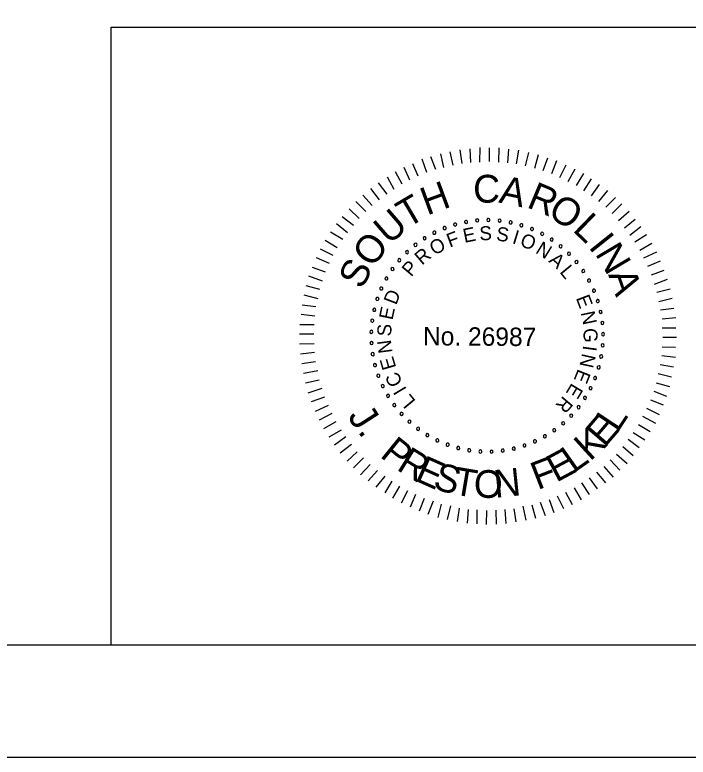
# Model space of a CAD drawing. Extents: x -305 to -161, y -187 to -99.
# Drawn here: x -216.35 to -204.37, y -187.49 to -174.27 of the extents above; entities that cross this region are included whole.
import ezdxf

# ---------------------------------------------------------------- set-up
doc = ezdxf.new("R2010")
doc.units = 0
for name, color, linetype in [('BR_BORDER LINES', 7, 'Continuous'), ('BR_TEXT', 7, 'Continuous'), ('Level 31', 7, 'Continuous')]:
    doc.layers.add(name, color=color, linetype=linetype)

msp = doc.modelspace()

# ---------------------------------------------------------------- linework, layer by layer
at = {"layer": 'BR_BORDER LINES'}
for p, q in [((-214.64, -174.489), (-193.18, -174.489)), ((-214.64, -185.489), (-214.64, -174.489)), ((-297.843, -185.489), (-163.178, -185.489))]:
    msp.add_line(p, q, dxfattribs=at)
at = {"layer": 'BR_TEXT'}
for p, q in [((-208.717, -176.986), (-208.77, -176.742)), ((-208.552, -176.946), (-208.608, -176.709)), ((-208.394, -176.917), (-208.429, -176.673)), ((-208.236, -176.901), (-208.251, -176.657)), ((-208.077, -176.892), (-208.075, -176.634)), ((-207.909, -176.883), (-207.907, -176.636)), ((-207.741, -176.895), (-207.732, -176.637)), ((-207.58, -176.906), (-207.561, -176.663)), ((-207.426, -176.925), (-207.382, -176.681)), ((-207.265, -176.957), (-207.208, -176.721)), ((-209.02, -177.076), (-209.103, -176.842)), ((-208.861, -177.026), (-208.949, -176.795)), ((-207.1, -176.999), (-207.036, -176.756)), ((-206.953, -177.042), (-206.865, -176.813)), ((-206.795, -177.095), (-206.708, -176.862)), ((-209.323, -177.211), (-209.427, -176.987)), ((-209.175, -177.144), (-209.269, -176.92)), ((-206.652, -177.165), (-206.54, -176.942)), ((-206.508, -177.234), (-206.383, -177.012)), ((-209.461, -177.282), (-209.582, -177.065)), ((-206.358, -177.308), (-206.229, -177.093)), ((-209.726, -177.462), (-209.883, -177.258)), ((-209.602, -177.377), (-209.724, -177.16)), ((-206.225, -177.405), (-206.089, -177.19)), ((-209.861, -177.564), (-210.021, -177.363)), ((-206.091, -177.492), (-205.946, -177.291)), ((-205.962, -177.596), (-205.799, -177.398)), ((-209.993, -177.662), (-210.159, -177.482)), ((-205.836, -177.696), (-205.663, -177.519)), ((-210.11, -177.771), (-210.287, -177.594)), ((-205.723, -177.807), (-205.55, -177.634)), ((-210.228, -177.894), (-210.402, -177.724)), ((-205.611, -177.932), (-205.421, -177.765)), ((-210.328, -178.02), (-210.526, -177.864)), ((-205.502, -178.06), (-205.316, -177.907)), ((-210.432, -178.153), (-210.63, -177.993)), ((-205.407, -178.194), (-205.21, -178.038)), ((-210.519, -178.269), (-210.735, -178.137)), ((-205.319, -178.312), (-205.109, -178.183)), ((-210.617, -178.416), (-210.832, -178.287)), ((-205.231, -178.46), (-205.017, -178.335)), ((-210.686, -178.552), (-210.912, -178.441)), ((-210.756, -178.699), (-210.985, -178.598)), ((-205.16, -178.598), (-204.929, -178.49)), ((-205.089, -178.746), (-204.862, -178.648)), ((-210.826, -178.853), (-211.059, -178.766)), ((-205.022, -178.901), (-204.795, -178.817)), ((-210.876, -179.014), (-211.122, -178.923)), ((-204.968, -179.063), (-204.738, -178.976)), ((-210.925, -179.158), (-211.168, -179.098)), ((-210.954, -179.326), (-211.204, -179.262)), ((-204.928, -179.207), (-204.688, -179.151)), ((-204.895, -179.376), (-204.654, -179.316)), ((-210.996, -179.47), (-211.24, -179.437)), ((-204.862, -179.52), (-204.625, -179.491)), ((-211.015, -179.634), (-211.261, -179.605)), ((-204.836, -179.685), (-204.592, -179.66)), ((-211.026, -179.792), (-211.284, -179.79)), ((-204.831, -179.843), (-204.59, -179.845)), ((-211.034, -179.957), (-211.285, -179.955)), ((-204.822, -180.008), (-204.578, -180.01)), ((-211.029, -180.129), (-211.286, -180.133)), ((-204.833, -180.18), (-204.593, -180.189)), ((-211.02, -180.283), (-211.267, -180.312)), ((-211.004, -180.448), (-211.248, -180.484)), ((-204.841, -180.334), (-204.598, -180.367)), ((-204.87, -180.499), (-204.634, -180.538)), ((-210.964, -180.606), (-211.215, -180.659)), ((-204.906, -180.656), (-204.666, -180.713)), ((-210.938, -180.775), (-211.182, -180.831)), ((-204.942, -180.824), (-204.702, -180.885)), ((-210.891, -180.923), (-211.139, -181.006)), ((-204.984, -180.971), (-204.755, -181.059)), ((-210.845, -181.077), (-211.079, -181.161)), ((-210.777, -181.226), (-211.008, -181.334)), ((-205.04, -181.125), (-204.814, -181.213)), ((-210.71, -181.37), (-210.937, -181.489)), ((-205.11, -181.272), (-204.884, -181.384)), ((-205.183, -181.416), (-204.954, -181.538)), ((-210.642, -181.519), (-210.859, -181.644)), ((-205.257, -181.563), (-205.045, -181.692)), ((-210.547, -181.667), (-210.765, -181.792)), ((-205.347, -181.71), (-205.139, -181.839)), ((-210.462, -181.784), (-210.663, -181.93)), ((-205.437, -181.826), (-205.243, -181.975)), ((-210.361, -181.919), (-210.561, -182.075)), ((-205.535, -181.959), (-205.351, -182.118)), ((-210.262, -182.054), (-210.439, -182.217)), ((-210.146, -182.158), (-210.326, -182.338)), ((-205.645, -182.092), (-205.458, -182.258)), ((-210.031, -182.279), (-210.2, -182.463)), ((-205.76, -182.194), (-205.589, -182.377)), ((-209.901, -182.383), (-210.064, -182.57)), ((-206.002, -182.415), (-205.842, -182.605)), ((-205.874, -182.313), (-205.704, -182.5)), ((-209.768, -182.487), (-209.928, -182.678)), ((-206.133, -182.517), (-205.99, -182.71)), ((-209.645, -182.574), (-209.77, -182.782)), ((-209.505, -182.664), (-209.63, -182.879)), ((-206.402, -182.69), (-206.277, -182.907)), ((-206.268, -182.602), (-206.135, -182.812)), ((-209.368, -182.744), (-209.477, -182.967)), ((-209.221, -182.814), (-209.319, -183.037)), ((-206.554, -182.768), (-206.432, -182.992)), ((-209.068, -182.884), (-209.155, -183.11)), ((-208.91, -182.933), (-209.001, -183.166)), ((-207.002, -182.949), (-206.918, -183.183)), ((-206.843, -182.902), (-206.759, -183.13)), ((-206.699, -182.835), (-206.591, -183.059)), ((-208.766, -182.983), (-208.823, -183.219)), ((-208.602, -183.011), (-208.662, -183.258)), ((-208.444, -183.057), (-208.484, -183.29)), ((-208.287, -183.076), (-208.306, -183.323)), ((-208.129, -183.087), (-208.131, -183.335)), ((-207.961, -183.099), (-207.963, -183.343)), ((-207.792, -183.09), (-207.787, -183.338)), ((-207.631, -183.081), (-207.616, -183.329)), ((-207.476, -183.065), (-207.437, -183.299)), ((-207.315, -183.022), (-207.262, -183.27)), ((-207.15, -182.996), (-207.09, -183.233))]:
    msp.add_line(p, q, dxfattribs=at)
for centre, start, end in [((-208.323, -177.957), 10.6038, 190.6038), ((-208.126, -177.93), 5.0653, 185.0653), ((-208.126, -177.93), 185.0653, 5.0653), ((-207.926, -177.923), 359.5268, 179.5268), ((-207.926, -177.923), 179.5268, 359.5268), ((-207.727, -177.934), 173.9884, 353.9884), ((-207.727, -177.934), 353.9884, 173.9884), ((-207.531, -177.965), 348.4499, 168.4499), ((-208.706, -178.067), 21.6807, 201.6807), ((-208.706, -178.067), 201.6807, 21.6807), ((-208.517, -178.003), 16.1422, 196.1422), ((-208.517, -178.003), 196.1422, 16.1422), ((-208.323, -177.957), 190.6038, 10.6038), ((-207.531, -177.965), 168.4499, 348.4499), ((-207.338, -178.015), 162.9114, 342.9114), ((-207.338, -178.015), 342.9114, 162.9114), ((-207.15, -178.083), 157.373, 337.373), ((-207.15, -178.083), 337.373, 157.373), ((-208.887, -178.149), 27.2191, 207.2191), ((-208.887, -178.149), 207.2191, 27.2191), ((-206.97, -178.169), 151.8345, 331.8345), ((-206.97, -178.169), 331.8345, 151.8345), ((-209.223, -178.364), 38.2961, 218.2961), ((-209.06, -178.248), 32.7576, 212.7576), ((-209.06, -178.248), 212.7576, 32.7576), ((-206.8, -178.272), 146.2961, 326.2961), ((-206.8, -178.272), 326.2961, 146.2961), ((-209.373, -178.495), 43.8345, 223.8345), ((-209.223, -178.364), 218.2961, 38.2961), ((-206.639, -178.39), 140.7576, 320.7576), ((-206.639, -178.39), 320.7576, 140.7576), ((-209.373, -178.495), 223.8345, 43.8345), ((-206.492, -178.524), 135.2191, 315.2191), ((-206.492, -178.524), 315.2191, 135.2191), ((-209.511, -178.639), 49.373, 229.373), ((-209.511, -178.639), 229.373, 49.373), ((-206.357, -178.671), 129.6807, 309.6807), ((-206.357, -178.671), 309.6807, 129.6807), ((-209.633, -178.796), 54.9114, 234.9114), ((-209.633, -178.796), 234.9114, 54.9114), ((-206.238, -178.831), 124.1422, 304.1422), ((-206.238, -178.831), 304.1422, 124.1422), ((-209.74, -178.964), 60.4499, 240.4499), ((-209.74, -178.964), 240.4499, 60.4499), ((-206.135, -179.001), 118.6038, 298.6038), ((-206.135, -179.001), 298.6038, 118.6038), ((-209.83, -179.142), 65.9884, 245.9884), ((-209.83, -179.142), 245.9884, 65.9884), ((-206.048, -179.181), 113.0653, 293.0653), ((-206.048, -179.181), 293.0653, 113.0653), ((-209.903, -179.328), 71.5268, 251.5268), ((-209.903, -179.328), 251.5268, 71.5268), ((-205.979, -179.368), 107.5268, 287.5268), ((-205.979, -179.368), 287.5268, 107.5268), ((-209.957, -179.52), 77.0653, 257.0653), ((-209.957, -179.52), 257.0653, 77.0653), ((-205.929, -179.561), 101.9884, 281.9884), ((-205.929, -179.561), 281.9884, 101.9884), ((-209.993, -179.716), 82.6038, 262.6038), ((-209.993, -179.716), 262.6038, 82.6038), ((-205.897, -179.758), 96.4499, 276.4499), ((-205.897, -179.758), 276.4499, 96.4499), ((-210.009, -179.914), 88.1422, 268.1422), ((-210.009, -179.914), 268.1422, 88.1422), ((-205.885, -179.957), 90.9114, 270.9114), ((-205.885, -179.957), 270.9114, 90.9114), ((-210.006, -180.114), 93.6807, 273.6807), ((-210.006, -180.114), 273.6807, 93.6807), ((-205.892, -180.156), 85.373, 265.373), ((-205.892, -180.156), 265.373, 85.373), ((-209.984, -180.312), 99.2191, 279.2191), ((-209.984, -180.312), 279.2191, 99.2191), ((-205.918, -180.353), 79.8345, 259.8345), ((-205.918, -180.353), 259.8345, 79.8345), ((-209.943, -180.507), 104.7576, 284.7576), ((-209.943, -180.507), 284.7576, 104.7576), ((-205.963, -180.548), 74.2961, 254.2961), ((-205.963, -180.548), 254.2961, 74.2961), ((-209.884, -180.697), 110.2961, 290.2961), ((-209.884, -180.697), 290.2961, 110.2961), ((-206.026, -180.737), 68.7576, 248.7576), ((-206.026, -180.737), 248.7576, 68.7576), ((-209.806, -180.881), 115.8345, 295.8345), ((-209.806, -180.881), 295.8345, 115.8345), ((-206.108, -180.918), 63.2191, 243.2191), ((-206.108, -180.918), 243.2191, 63.2191), ((-209.711, -181.056), 121.373, 301.373), ((-209.711, -181.056), 301.373, 121.373), ((-206.207, -181.092), 57.6807, 237.6807), ((-206.207, -181.092), 237.6807, 57.6807), ((-209.599, -181.221), 126.9114, 306.9114), ((-209.599, -181.221), 306.9114, 126.9114), ((-206.321, -181.255), 52.1422, 232.1422), ((-206.321, -181.255), 232.1422, 52.1422), ((-209.472, -181.375), 132.4499, 312.4499), ((-209.472, -181.375), 312.4499, 132.4499), ((-206.452, -181.406), 46.6038, 226.6038), ((-209.331, -181.515), 137.9884, 317.9884), ((-209.331, -181.515), 317.9884, 137.9884), ((-206.452, -181.406), 226.6038, 46.6038), ((-209.177, -181.642), 143.5268, 323.5268), ((-209.177, -181.642), 323.5268, 143.5268), ((-206.752, -181.667), 35.5268, 215.5268), ((-206.596, -181.543), 41.0653, 221.0653), ((-206.596, -181.543), 221.0653, 41.0653), ((-209.011, -181.753), 149.0653, 329.0653), ((-209.011, -181.753), 329.0653, 149.0653), ((-206.92, -181.774), 29.9884, 209.9884), ((-206.92, -181.774), 209.9884, 29.9884), ((-206.752, -181.667), 215.5268, 35.5268), ((-208.836, -181.847), 154.6038, 334.6038), ((-208.836, -181.847), 334.6038, 154.6038), ((-208.652, -181.924), 340.1422, 160.1422), ((-207.098, -181.865), 24.4499, 204.4499), ((-207.098, -181.865), 204.4499, 24.4499), ((-208.652, -181.924), 160.1422, 340.1422), ((-208.462, -181.983), 165.6807, 345.6807), ((-208.462, -181.983), 345.6807, 165.6807), ((-208.267, -182.023), 171.2191, 351.2191), ((-208.267, -182.023), 351.2191, 171.2191), ((-208.068, -182.045), 356.7576, 176.7576), ((-207.869, -182.047), 2.2961, 182.2961), ((-207.67, -182.029), 7.8345, 187.8345), ((-207.67, -182.029), 187.8345, 7.8345), ((-207.474, -181.993), 13.373, 193.373), ((-207.474, -181.993), 193.373, 13.373), ((-207.283, -181.938), 18.9114, 198.9114), ((-207.283, -181.938), 198.9114, 18.9114), ((-208.068, -182.045), 176.7576, 356.7576), ((-207.869, -182.047), 182.2961, 2.2961)]:
    msp.add_arc(centre, 0.028, start, end, dxfattribs=at)
at = {"layer": 'Level 31'}
msp.add_lwpolyline([(-305.176, -187.489), (-161.176, -187.489), (-161.176, -99.489), (-305.176, -99.489)], close=True, dxfattribs=at)

# ---------------------------------------------------------------- texts
at = {"layer": 'BR_TEXT'}
for s, height, rotation, p in [('C', 0.496, 359.5482, (-208.2, -177.612)), ('H', 0.496, 20.3637, (-209.018, -177.846)), ('A', 0.496, 348.1981, (-207.755, -177.609)), ('R', 0.496, 337.4344, (-207.262, -177.689)), ('T', 0.496, 30.4992, (-209.37, -178.076)), ('O', 0.496, 326.5869, (-206.893, -177.836)), ('U', 0.496, 40.8022, (-209.694, -178.375)), ('L', 0.496, 315.9488, (-206.442, -178.107)), ('E', 0.249, 11.4103, (-208.352, -178.33)), ('S', 0.249, 2.208, (-208.081, -178.286)), ('S', 0.249, 352.6608, (-207.796, -178.287)), ('O', 0.496, 52.0267, (-209.993, -178.79)), ('F', 0.249, 20.6127, (-208.613, -178.417)), ('I', 0.249, 343.1136, (-207.515, -178.335)), ('O', 0.249, 338.4392, (-207.381, -178.376)), ('I', 0.496, 308.6613, (-206.157, -178.404)), ('O', 0.249, 30.8477, (-208.882, -178.561)), ('N', 0.249, 328.2042, (-207.103, -178.501)), ('N', 0.496, 300.7037, (-206.035, -178.521)), ('R', 0.249, 40.3949, (-209.107, -178.737)), ('A', 0.249, 318.657, (-206.867, -178.662)), ('S', 0.496, 63.2511, (-210.174, -179.173)), ('P', 0.249, 49.9421, (-209.299, -178.947)), ('L', 0.249, 309.4546, (-206.668, -178.851)), ('A', 0.496, 289.4792, (-205.798, -178.894)), ('D', 0.249, 69.0364, (-209.567, -179.448)), ('E', 0.249, 291.049, (-206.372, -179.312)), ('E', 0.249, 78.2388, (-209.633, -179.715)), ('N', 0.249, 281.8466, (-206.283, -179.572)), ('S', 0.249, 87.786, (-209.656, -179.999)), ('No. 26987', 0.327, 359.5268, (-209.092, -180.153)), ('G', 0.249, 272.2995, (-206.237, -179.853)), ('N', 0.249, 97.3332, (-209.632, -180.283)), ('I', 0.249, 262.4084, (-206.238, -180.149)), ('N', 0.249, 257.7339, (-206.256, -180.287)), ('E', 0.249, 106.5355, (-209.564, -180.549)), ('C', 0.249, 116.4266, (-209.444, -180.819)), ('E', 0.249, 248.1867, (-206.328, -180.563)), ('E', 0.249, 238.9844, (-206.44, -180.814)), ('I', 0.249, 121.1011, (-209.372, -180.939)), ('L', 0.249, 129.9595, (-209.209, -181.147)), ('R', 0.249, 229.782, (-206.591, -181.044)), ('J', 0.494, 302.9559, (-210.441, -181.421)), ('E', 0.494, 49.3639, (-205.857, -181.989)), ('L', 0.494, 56.4247, (-205.627, -181.718)), ('K', 0.494, 42.3031, (-206.118, -182.229)), ('.', 0.494, 309.3974, (-210.264, -181.693)), ('P', 0.494, 321.1035, (-209.871, -182.13)), ('R', 0.494, 328.5359, (-209.578, -182.362)), ('E', 0.494, 28.1814, (-206.719, -182.605)), ('L', 0.494, 35.2422, (-206.407, -182.436)), ('E', 0.494, 335.9684, (-209.257, -182.555)), ('F', 0.494, 21.1206, (-207.05, -182.735)), ('S', 0.494, 343.0292, (-208.932, -182.698)), ('T', 0.494, 350.4617, (-208.573, -182.804)), ('O', 0.494, 358.1419, (-208.192, -182.863)), ('N', 0.494, 5.8221, (-207.805, -182.872))]:
    msp.add_text(s, height=height, rotation=rotation, dxfattribs=at).set_placement(p)

doc.saveas('drawing.dxf')
